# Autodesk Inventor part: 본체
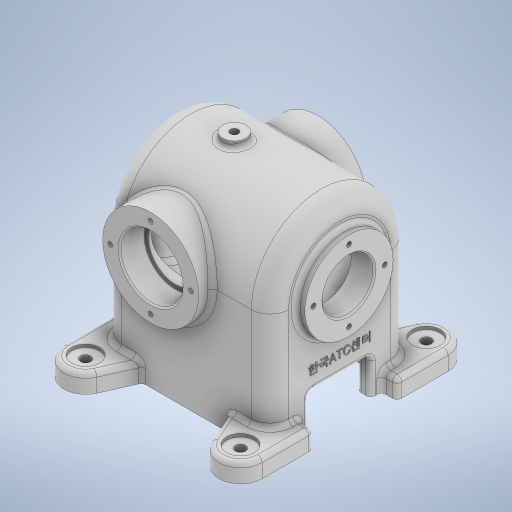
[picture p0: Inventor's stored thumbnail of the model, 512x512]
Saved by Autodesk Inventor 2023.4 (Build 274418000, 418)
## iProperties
Created: 2024-09
Part Number: 본체
Material: 일반
Document SubType Name: Modeling
Designer: EDU
Density: 1 g/cm^3
Appearance: 기본값
Author: EDU
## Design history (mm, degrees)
sketch "스케치1"
  geometry: L1 (0, 45)-(-76, 45); L2 (0, -45)-(-76, -45); L3 (-76, 45)-(-76, -45); A1 r 45 centre (0, 0) between (0, 45) and (0, -45); 1 further point
  constraints: 6 end point, 2 horizontal, 2 point on circle, 2 tangent, 1 centre point, 1 coincident, 1 vertical
  dimensions: "d0" = 90 diameter of A1; "d1" = 76 distance of L1.start L1.end
extrude "돌출1" new body sketch "스케치1" distance "d2" = 108; taper "d3" = 0 deg
feature "쉘1" dims "d4" = 9
sketch "스케치2"
  geometry: C1 r 45 at (0, 0); C2 r 36 at (0, 0); A1 r 45 centre (0, 0) between (45, 0) and (-45, 0) reference; 3 further points
  constraints: 2 centre point, 1 coincident
  dimensions: "d5" = 90 diameter of C1; "d6" = 9 radial gap between concentric circles of C1 C2
extrude "돌출2" join sketch "스케치2" distance "d7" = 108; taper "d8" = 0 deg
sketch "스케치3"
  geometry: L1 (-45, 0)-(-45, -76) reference; L2 (-45, -76)-(45, -76) reference; L3 (45, -76)-(45, 0) reference; L4 (-45, -76)-(45, -76) reference; L5 (20, -53)-(-20, -53); L6 (-20, -53)-(-20, -76); L7 (-20, -76)-(20, -76); L8 (20, -76)-(20, -53); A1 r 45 centre (0, 0) between (45, 0) and (-45, 0) reference; 7 further points
  constraints: 8 end point, 4 midpoint, 2 parallel, 1 coincident, 1 horizontal, 1 perpendicular, 1 point on line, 1 vertical alignment
  dimensions: "d9" = 23 distance between parallel lines of L2 L5; "d10" = 40 distance between parallel lines of L6 L8
extrude "돌출3" cut sketch "스케치3" distance "d11" = 108; taper "d12" = 0 deg
sketch "스케치4"
  geometry: L1 (-20, -76)-(-20, -53) reference; L2 (-20, -53)-(20, -53) reference; L3 (20, -53)-(20, -76) reference; L4 (20, -76)-(45, -76) reference; L5 (45, -76)-(45, 0) reference; L6 (-45, 0)-(-45, -76) reference; L7 (-45, -76)-(-20, -76) reference; C1 r 28.5 at (0, 0); A1 r 45 centre (0, 0) between (45, 0) and (-45, 0) reference; 1 further point
  constraints: 1 centre point, 1 coincident
  dimensions: "d13" = 57 diameter of C1
extrude "돌출4" join sketch "스케치4" distance "d14" = 6; taper "d15" = 0 deg
sketch "스케치5"
  geometry: C1 r 28.5 at (0, 0) reference; C2 r 16.5 at (0, 0); 1 further point
  constraints: 1 centre point, 1 coincident
  dimensions: "d16" = 33 diameter of C2
extrude "돌출5" cut sketch "스케치5" distance "d17" = 15; taper "d18" = 0 deg
chamfer "모따기1" distance "d19" = 1; stored, may be unused: second distance "d20" = 2, angle "d21" = 45 deg
sketch "스케치6"
  geometry: L1 (0, 76)-(0, 0) reference; L2 (0, 0)-(108, 0) reference; L3 (108, 76)-(108, 0) reference; L4 (0, 76)-(108, 76) reference; L5 (0, 76)-(108, 76) reference; L6 (114, 47.5)-(114, 104.5) reference; C1 r 31 at (40, 76); 1 further point
  constraints: 1 centre point, 1 midpoint, 1 point on line
  dimensions: "d22" = 62 diameter of C1; "d23" = 74 distance of point (114, 76) C1.centre
extrude "돌출6" join sketch "스케치6" distance "d24" = 9; taper "d25" = 0 deg
sketch "스케치7"
  geometry: L1 (-9, 76)-(-71, 76) reference; A1 r 31 centre (-40, 76) between (-9, 76) and (-71, 76) reference; 1 further point
extrude "돌출7" join sketch "스케치7" stored distance "d26" = 9; taper "d27" = 0 deg
sketch "스케치8"
  geometry: L1 (-31, 0)-(31, 0) reference; A1 r 31 centre (0, 0) between (31, 0) and (-31, 0) reference; 1 further point
extrude "돌출8" join sketch "스케치8" stored distance "d28" = 10; taper "d29" = 0 deg
sketch "스케치9"
  geometry: C1 r 31 at (0, 0) reference; C2 r 17.5 at (0, 0); 1 further point
  constraints: 1 centre point, 1 coincident
  dimensions: "d30" = 35 diameter of C2
extrude "돌출9" cut sketch "스케치9" extent not by distance; stored distance "d31" = 0; taper "d32" = 0 deg
sketch "스케치10"
  geometry: C1 r 17.5 at (0, 0) reference; C2 r 31 at (0, 0) reference; C3 r 20 at (0, 0); 1 further point
  constraints: 1 centre point, 1 coincident
  dimensions: "d33" = 40 diameter of C3
extrude "돌출10" cut sketch "스케치10" distance "d34" = 16; taper "d35" = 0 deg
chamfer "모따기2" distance "d36" = 1; stored, may be unused: second distance "d37" = 2, angle "d38" = 45 deg
chamfer "모따기3" distance "d39" = 1; stored, may be unused: second distance "d40" = 2, angle "d41" = 45 deg
fillet "모깎기1" dims "d42" = 0.3
sketch "스케치11"
  geometry: L1 (0, -25)-(9, -25) reference; L2 (9, -25)-(9, -9) reference; L3 (9, -9)-(99, -9) reference; L4 (99, -9)-(99, -25) reference; L5 (99, -25)-(108, -25) reference; L6 (108, 0)-(108, -25) reference; L7 (0, 0)-(108, 0) reference; L8 (0, 0)-(0, -25) reference; L9 (9, -65)-(0, -65) reference; L10 (0, -65)-(0, -90) reference; L11 (0, -90)-(108, -90) reference; L12 (108, -65)-(108, -90) reference; L13 (108, -65)-(99, -65) reference; L14 (99, -65)-(99, -81) reference; L15 (99, -81)-(9, -81) reference; L16 (9, -81)-(9, -65) reference; L17 (0, -65)-(0, -25) reference; L18 (61, 9)-(19, 9) reference; L19 (-10, 15)-(-10, -18); L20 (-10, -18)-(0, -18); L21 (9, 9)-(9, 0) reference; L22 (71, 9)-(9, 9) reference; L23 (108, 0)-(108, -25) reference; L24 (118, 15)-(118, -18); L25 (118, -18)-(108, -18); L26 (16.79, 20.693)-(26, 0); L27 (0, 0)-(108, 0) reference; L28 (91.21, 20.693)-(82, 0); A1 r 14 centre (4, 15) between (-10, 15) and (16.79, 20.693); A2 r 14 centre (104, 15) between (118, 15) and (91.21, 20.693); 9 further points
  constraints: 12 end point, 4 midpoint, 4 point on circle, 4 point on line, 4 tangent, 3 horizontal alignment, 2 centre point, 2 vertical, 1 horizontal, 1 perpendicular
  dimensions: "d46" = 28 diameter of A1; "d47" = 28 diameter of A2; "d48" = 100 distance of A2.centre A1.centre; "d50" = 18 distance between parallel lines of L20 L7; "d51" = 10 distance of L19.end L20.end; "d54" = 60 vertical distance of point (0, -45) A1.centre; "d55" = 36 distance from line of L26.end L19; "d56" = 36 distance from line of L28.end L24
extrude "돌출11" join sketch "스케치11" distance "d57" = 12; taper "d58" = 0 deg
node "작업 평면1"
sketch "스케치12"
  geometry: L1 (105, 7.5)-(105, 64.5) reference; L2 (-9, 16)-(-9, 56) reference; L3 (62, 90)-(0, 90) reference; L4 (62, -18)-(0, -18) reference; C1 r 7.5 at (31, 36); 3 further points
  constraints: 2 midpoint, 1 centre point, 1 horizontal alignment
  dimensions: "d60" = 15 diameter of C1; "d61" = 74 distance of point (105, 36) C1.centre
extrude "돌출12" join sketch "스케치12" stored distance "d62" = 12; taper "d63" = 0 deg
sketch "스케치13"
  geometry: L1 (-40, -45)-(-40, 45) reference; L2 (-40, 45)-(-31, 45) reference; L3 (-40, 45)-(-40, -45) reference; L4 (-40, -45)-(-31, -45) reference; L5 (31, -45)-(68, -45) reference; L6 (68, 45)-(68, -45) reference; L7 (31, 45)-(68, 45) reference; L8 (-31, 54)-(31, 54) reference; C1 r 7.5 at (0, 0) reference; 5 further points
  constraints: 3 horizontal alignment, 2 midpoint, 1 coincident, 1 vertical alignment, 1 other
hole "구멍1" sketch "스케치13" at (0, 0) diameter "d64" = 5.1881; stored, may be unused: countersink angle "d68" = 90 deg, drill point angle "d70" = 118 deg; dims "d65" = 150, "d66" = 4, "d67" = 2, "d69" = 16
sketch "스케치14" dims "d71" = 46
  geometry: C1 r 28.5 at (0, 0) reference; C2 r 17.5 at (0, 0) reference; 6 further points
  constraints: 2 vertical alignment, 1 coincident, 7 other
  dimensions: "d74" = 360 deg dimension on C2.centre point (0, 23) (derived)
hole "구멍2" sketch "스케치14" at (0, 23), (-23, 0), (0, -23), (23, 0) diameter "d76" = 3.242; stored, may be unused: countersink angle "d80" = 90 deg, drill point angle "d82" = 118 deg; dims "d77" = 8, "d78" = 4, "d79" = 2, "d81" = 10
sketch "스케치15" dims "d83" = 52
  geometry: C1 r 31 at (0, 0) reference; C2 r 21 at (0, 0) reference; 6 further points
  constraints: 2 vertical alignment, 1 coincident, 7 other
  dimensions: "d86" = 360 deg dimension on C2.centre point (0, 26) (derived)
hole "구멍3" sketch "스케치15" at (0, 26), (-26, 0), (0, -26), (26, 0) diameter "d88" = 3.242; stored, may be unused: countersink angle "d92" = 90 deg, drill point angle "d94" = 118 deg; dims "d89" = 8, "d90" = 4, "d91" = 2, "d93" = 10
fillet "모깎기2" dims "d95" = 12
fillet "모깎기3" dims "d96" = 3
sketch "스케치16"
  geometry: A1 r 14 centre (4, -15) between (-10, -15) and (16.79, -20.693) reference; 5 further points
  constraints: 2 horizontal alignment, 2 vertical alignment, 1 coincident
  dimensions: "d97" = 100 distance of point (104, -15) point (4, -15); "d98" = 120 distance of point (4, 105) point (4, -15)
hole "구멍4" sketch "스케치16" at (4, -15), (104, -15), (4, 105), (104, 105) diameter "d99" = 6.6; stored, may be unused: countersink angle "d103" = 82 deg, drill point angle "d105" = 0 deg; dims "d100" = 8, "d101" = 18, "d102" = 2, "d104" = 12
sketch "스케치17"
  geometry: L1 (-20, -53)-(20, -53) reference; L2 (-20.763, -37.998)-(20.763, -37.998); L3 (20.763, -37.998)-(20.763, -44.002); L4 (20.763, -44.002)-(-20.763, -44.002); L5 (-20.763, -44.002)-(-20.763, -37.998); L6 (-27, -76)-(-60, -76) reference; C1 r 33 at (0, 0) reference; 3 further points
  constraints: 2 midpoint, 1 vertical alignment, 2 other
  dimensions: "d106" = 35 distance from line of L6 point (-20.763, -41)
feature "엠보싱1" sketch "스케치17" dims "d107" = 0.5, "d108" = 0
fillet "모깎기4" dims "d109" = 3
fillet "모깎기5" dims "d110" = 3
fillet "모깎기6" dims "d111" = 3
fillet "모깎기7" dims "d112" = 3
fillet "모깎기10" dims "d115" = 3
fillet "모깎기11" dims "d116" = 3
fillet "모깎기12" dims "d117" = 3
node "솔리드1"
mirror "미러1"
mirror "미러2"
mirror "미러3"
mirror "미러4"
mirror "미러5"
node "투영된 루프1"
node "투영된 루프2"
node "투영된 루프3"
node "투영된 루프4"
node "투영된 루프5"
node "투영된 루프6"
node "투영된 루프7"
node "투영된 루프8"
node "투영된 루프9"
node "투영된 루프10"
node "투영된 루프11"
node "투영된 루프12"
node "투영된 루프13"
node "투영된 루프14"
feature "A9D066F2-1C7D-4E18-AEED-F7BC21143FA4" dims "d99" = 6.6, "d100" = 8, "d101" = 18, "d102" = 2, "d103" = 82 deg, "d104" = 12, "d105" = 0
other parameters: "d59" = -125
